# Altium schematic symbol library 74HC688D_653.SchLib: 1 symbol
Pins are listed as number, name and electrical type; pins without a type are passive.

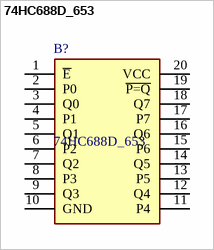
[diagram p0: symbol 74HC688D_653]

## 74HC688D_653
designator B?
74HC688 - 8-bit magnitude comparator@en-us; Manufacturer_Name: Nexperia; Manufacturer_Part_Number: 74HC688D,653; Geometry.Height: 2.65mm
footprint SOIC127P1032X265-20N
pins: 1 ~{E}, 2 P0, 3 Q0, 4 P1, 5 Q1, 6 P2, 7 Q2, 8 P3, 9 Q3, 10 GND, 11 P4, 12 Q4, 13 P5, 14 Q5, 15 P6, 16 Q6, 17 P7, 18 Q7, 19 ~{P=Q}, 20 VCC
